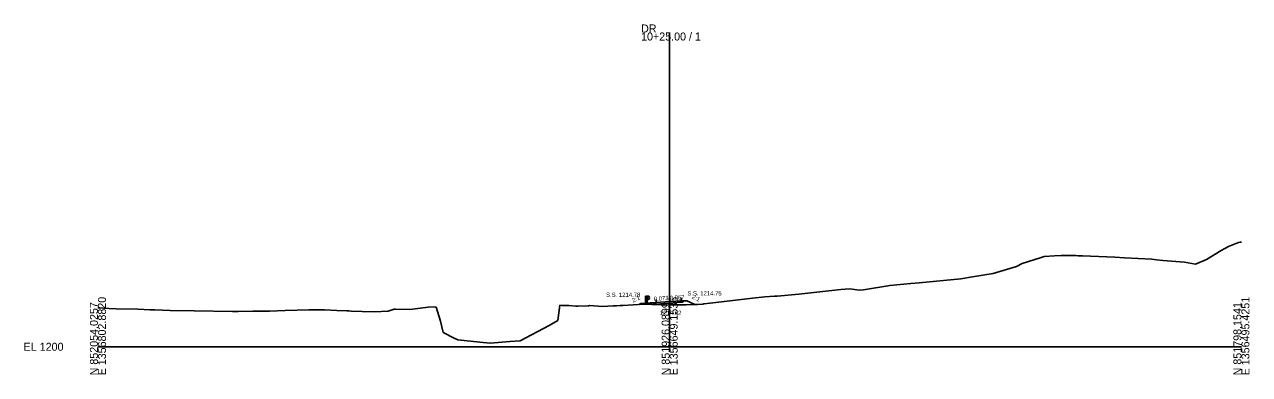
# Model space of a CAD drawing. Extents: x -26 to 1356684, y -10 to 851918.
# Drawn here: x 1374.3 to 1802.8, y -9.7 to 112.7 of the extents above; entities that cross this region are included whole.
import ezdxf

# ---------------------------------------------------------------- set-up
doc = ezdxf.new("R2010")
doc.units = 0
for name, color, linetype in [('Exist Cross Section Cell', 7, 'Continuous'), ('Exist XS Center Line Elevation Label', 7, 'Continuous'), ('Exist XS Ground Line', 7, 'Continuous'), ('Prop XS Ditch Slope Text', 7, 'Continuous'), ('Prop XS Dump Level', 7, 'Continuous'), ('Prop XS Earthwork Shape', 7, 'Continuous'), ('Prop XS EOT Tick Mark', 7, 'Continuous'), ('Prop XS Finish Grade', 7, 'Continuous'), ('Prop XS Finish Grade Earthwork', 7, 'Continuous'), ('Prop XS Finish Grade Pavement', 7, 'Continuous'), ('Prop XS Guardrail', 7, 'Continuous'), ('Prop XS Pvmt Edge Slope', 7, 'Continuous'), ('Prop XS SE Text', 7, 'Continuous'), ('Prop XS SS Elevation Text', 7, 'Continuous'), ('Prop XS Subgrade Earthwork', 7, 'Continuous')]:
    doc.layers.add(name, color=color, linetype=linetype)

msp = doc.modelspace()

# ---------------------------------------------------------------- linework, layer by layer
at = {"layer": 'Exist Cross Section Cell'}
for p, q in [((1600, 0), (1600, 109.92)), ((1400, 0), (1600, 0)), ((1600, 0), (1800, 0))]:
    msp.add_line(p, q, dxfattribs=at)
at = {"layer": 'Exist XS Ground Line'}
for p, q in [((1792.93, 33.65), (1795.5, 35.06)), ((1795.5, 35.06), (1799.05, 36.53)), ((1799.05, 36.53), (1799.55, 36.59)), ((1799.55, 36.59), (1800, 36.64)), ((1723.35, 29.11), (1729.59, 31.14)), ((1729.59, 31.14), (1731.01, 31.62)), ((1731.01, 31.62), (1734.6, 31.77)), ((1734.6, 31.77), (1736.96, 31.87)), ((1736.96, 31.87), (1737.55, 31.9)), ((1737.55, 31.9), (1740.11, 31.89)), ((1740.11, 31.89), (1742.13, 31.89)), ((1742.13, 31.89), (1742.89, 31.86)), ((1742.89, 31.86), (1744.44, 31.79)), ((1744.44, 31.79), (1755.72, 31.33)), ((1755.72, 31.33), (1759.08, 31.14)), ((1759.08, 31.14), (1768.73, 30.6)), ((1768.73, 30.6), (1770.35, 30.43)), ((1770.35, 30.43), (1772.56, 30.19)), ((1772.56, 30.19), (1780.08, 29.62)), ((1783.99, 28.89), (1787.84, 30.55)), ((1787.84, 30.55), (1792.93, 33.65)), ((1713.13, 25.64), (1721.29, 28.06)), ((1721.29, 28.06), (1723.35, 29.11)), ((1780.08, 29.62), (1782.63, 29.14)), ((1782.63, 29.14), (1783.99, 28.89)), ((1667.81, 19.95), (1677, 21.44)), ((1677, 21.44), (1684.42, 22.14)), ((1684.42, 22.14), (1687.26, 22.42)), ((1687.26, 22.42), (1701.82, 23.81)), ((1701.82, 23.81), (1705.92, 24.43)), ((1705.92, 24.43), (1713.13, 25.64)), ((1628.97, 16.96), (1633.35, 17.49)), ((1633.35, 17.49), (1636.65, 17.7)), ((1636.65, 17.7), (1637.27, 17.73)), ((1637.27, 17.73), (1637.66, 17.75)), ((1637.66, 17.75), (1645.22, 18.45)), ((1645.22, 18.45), (1659.89, 20)), ((1659.89, 20), (1662.91, 20.23)), ((1662.91, 20.23), (1663.82, 20.19)), ((1663.82, 20.19), (1666.25, 19.85)), ((1666.25, 19.85), (1667.81, 19.95)), ((1400, 13.61), (1403.78, 13.43)), ((1403.78, 13.43), (1406.33, 13.33)), ((1406.33, 13.33), (1413.93, 13.1)), ((1413.93, 13.1), (1418.23, 12.94)), ((1418.23, 12.94), (1419.57, 12.92)), ((1419.57, 12.92), (1419.95, 12.87)), ((1419.95, 12.87), (1425.21, 12.71)), ((1465.46, 12.66), (1473.82, 12.95)), ((1473.82, 12.95), (1474.55, 12.97)), ((1474.55, 12.97), (1475.31, 12.97)), ((1475.31, 12.97), (1479.2, 12.91)), ((1479.2, 12.91), (1483.56, 12.65)), ((1501.57, 12.44), (1503.67, 13.14)), ((1503.67, 13.14), (1504.04, 13.16)), ((1504.04, 13.16), (1509.13, 13.07)), ((1509.13, 13.07), (1515.57, 13.87)), ((1515.57, 13.87), (1517.89, 13.93)), ((1517.89, 13.93), (1518.32, 13.91)), ((1518.32, 13.91), (1519.78, 9.01)), ((1560.92, 9.22), (1561.63, 14.54)), ((1561.63, 14.54), (1562.2, 14.49)), ((1562.2, 14.49), (1564.76, 14.47)), ((1564.76, 14.47), (1567.23, 14.25)), ((1567.23, 14.25), (1567.85, 14.26)), ((1567.85, 14.26), (1571.57, 14.32)), ((1571.57, 14.32), (1572, 14.38)), ((1572, 14.38), (1576.47, 14.14)), ((1576.47, 14.14), (1580.19, 14.29)), ((1580.19, 14.29), (1580.81, 14.31)), ((1580.81, 14.31), (1581.45, 14.32)), ((1581.45, 14.32), (1582.69, 14.4)), ((1582.69, 14.4), (1583.67, 14.47)), ((1583.67, 14.47), (1590.86, 14.86)), ((1590.86, 14.86), (1593.77, 14.76)), ((1593.77, 14.76), (1597.03, 14.62)), ((1597.03, 14.62), (1597.69, 14.61)), ((1597.69, 14.61), (1600, 14.62)), ((1600, 14.62), (1605.74, 14.65)), ((1605.74, 14.65), (1608.6, 14.74)), ((1608.6, 14.74), (1609.68, 14.8)), ((1609.68, 14.8), (1611.6, 14.93)), ((1611.6, 14.93), (1611.9, 14.98)), ((1611.9, 14.98), (1614.12, 15.28)), ((1614.12, 15.28), (1628.97, 16.96)), ((1425.21, 12.71), (1433.62, 12.56)), ((1433.62, 12.56), (1447.03, 12.32)), ((1447.03, 12.32), (1447.84, 12.35)), ((1447.84, 12.35), (1448.18, 12.34)), ((1448.18, 12.34), (1449.02, 12.34)), ((1449.02, 12.34), (1454.16, 12.46)), ((1454.16, 12.46), (1455.18, 12.45)), ((1455.18, 12.45), (1460.04, 12.43)), ((1460.04, 12.43), (1465.46, 12.66)), ((1483.56, 12.65), (1487.12, 12.52)), ((1487.12, 12.52), (1487.82, 12.52)), ((1487.82, 12.52), (1488.63, 12.46)), ((1488.63, 12.46), (1492.47, 12.38)), ((1492.47, 12.38), (1496.75, 12.22)), ((1496.75, 12.22), (1501.57, 12.44)), ((1519.78, 9.01), (1520.76, 4.94)), ((1557.88, 7.47), (1560.92, 9.22)), ((1520.76, 4.94), (1524.63, 3.01)), ((1547.65, 2.04), (1557.88, 7.47)), ((1524.63, 3.01), (1525.86, 2.45)), ((1525.86, 2.45), (1533.61, 1.61)), ((1533.61, 1.61), (1537.19, 1.21)), ((1537.19, 1.21), (1544.04, 1.85)), ((1544.04, 1.85), (1547.65, 2.04))]:
    msp.add_line(p, q, dxfattribs=at)
at = {"layer": 'Prop XS Dump Level'}
for p, q in [((1600, 15.84), (1595.29, 15.5)), ((1604, 16.11), (1600, 15.84))]:
    msp.add_line(p, q, dxfattribs=at)
at = {"layer": 'Prop XS Earthwork Shape'}
msp.add_lwpolyline([(1589.32, 14.78), (1590.86, 14.86), (1593.77, 14.76), (1597.03, 14.62), (1597.69, 14.61), (1600, 14.62), (1605.74, 14.65), (1608.6, 14.74), (1608.75, 14.75), (1606, 16.12), (1605.02, 16.11), (1604.5, 15.6), (1604, 15.57), (1600, 15.3), (1595.29, 14.96), (1594.66, 14.91), (1594.13, 15.41), (1593.15, 15.34), (1589.92, 15.08)], close=True, dxfattribs=at)
at = {"layer": 'Prop XS EOT Tick Mark'}
for p, q in [((1595.29, 15.5), (1595.29, 16.5)), ((1604, 16.11), (1604, 17.11))]:
    msp.add_line(p, q, dxfattribs=at)
at = {"layer": 'Prop XS Finish Grade'}
for p, q in [((1595.29, 15.5), (1594.13, 15.41)), ((1604, 16.11), (1605.02, 16.11))]:
    msp.add_line(p, q, dxfattribs=at)
at = {"layer": 'Prop XS Finish Grade Earthwork'}
for p, q in [((1589.92, 15.08), (1589.32, 14.78)), ((1593.15, 15.34), (1589.92, 15.08)), ((1594.13, 15.41), (1593.15, 15.34)), ((1605.02, 16.11), (1606, 16.12)), ((1606, 16.12), (1608.75, 14.75))]:
    msp.add_line(p, q, dxfattribs=at)
at = {"layer": 'Prop XS Finish Grade Pavement'}
for p, q in [((1595.29, 15.5), (1600, 15.84)), ((1600, 15.84), (1604, 16.11))]:
    msp.add_line(p, q, dxfattribs=at)
at = {"layer": 'Prop XS Guardrail'}
for p, q in [((1591.6, 17.7), (1592.1, 17.7)), ((1591.6, 15.2), (1591.6, 17.7)), ((1592.1, 17.7), (1592.6, 17.7)), ((1592.1, 17.7), (1592.1, 15.2)), ((1592.6, 17.7), (1592.89, 17.5)), ((1592.89, 17.38), (1592.6, 17.18)), ((1592.6, 17.18), (1592.6, 17.09)), ((1592.89, 17.5), (1592.92, 17.44)), ((1592.92, 17.44), (1592.89, 17.38)), ((1592.6, 16.57), (1592.1, 16.57)), ((1592.6, 17.09), (1592.89, 16.89)), ((1592.89, 16.77), (1592.6, 16.57)), ((1592.89, 16.89), (1592.92, 16.83)), ((1592.92, 16.83), (1592.89, 16.77))]:
    msp.add_line(p, q, dxfattribs=at)
at = {"layer": 'Prop XS Pvmt Edge Slope'}
for p, q in [((1595.29, 15.5), (1594.66, 14.91)), ((1604, 16.11), (1604.5, 15.6))]:
    msp.add_line(p, q, dxfattribs=at)
at = {"layer": 'Prop XS Subgrade Earthwork'}
for p, q in [((1594.66, 14.91), (1594.13, 15.41)), ((1595.29, 14.96), (1594.66, 14.91)), ((1600, 15.3), (1595.29, 14.96)), ((1604, 15.57), (1600, 15.3)), ((1604, 15.57), (1604.5, 15.6)), ((1604.5, 15.6), (1605.02, 16.11))]:
    msp.add_line(p, q, dxfattribs=at)

# ---------------------------------------------------------------- texts
at = {"layer": 'Exist Cross Section Cell'}
for s, p in [('DR', (1590, 109.92)), ('10+25.00 / 1', (1590, 107.12)), ('EL 1200', (1374, -1.4))]:
    msp.add_text(s, height=2.8, dxfattribs=at).set_placement(p)
for s, p in [('E 1356802.8820', (1402.8, -10)), ('E 1356649.1536', (1602.8, -10)), ('E 1356495.4251', (1802.8, -10)), ('N 852054.0257', (1400, -10)), ('N 851926.0899', (1600, -10)), ('N 851798.1541', (1800, -10))]:
    msp.add_text(s, height=2.8, rotation=90, dxfattribs=at).set_placement(p)
at = {"layer": 'Exist XS Center Line Elevation Label'}
msp.add_text('1214.62', height=1.5, dxfattribs=at).set_placement((1596.6, 11.12))
at = {"layer": 'Prop XS Ditch Slope Text'}
for rotation, p in [(26.5651, (1587.25, 15.42)), (333.4349, (1607.6, 16.99))]:
    msp.add_text('2:1', height=1.5, rotation=rotation, dxfattribs=at).set_placement(p)
at = {"layer": 'Prop XS Dump Level'}
for p in [(1593.15, 15.3), (1606, 16.08)]:
    msp.add_text('Case1', height=0.04, dxfattribs=at).set_placement(p)
at = {"layer": 'Prop XS SE Text'}
for s, rotation, p in [('0.073', 4.1477, (1594.5, 15.98)), ('0.067', 3.8282, (1600.07, 16.3))]:
    msp.add_text(s, height=1.5, rotation=rotation, dxfattribs=at).set_placement(p)
at = {"layer": 'Prop XS SS Elevation Text'}
for s, p in [('S.S. 1214.78', (1577.76, 17.44)), ('S.S. 1214.75', (1606.21, 17.94))]:
    msp.add_text(s, height=1.5, dxfattribs=at).set_placement(p)

doc.saveas('drawing.dxf')
